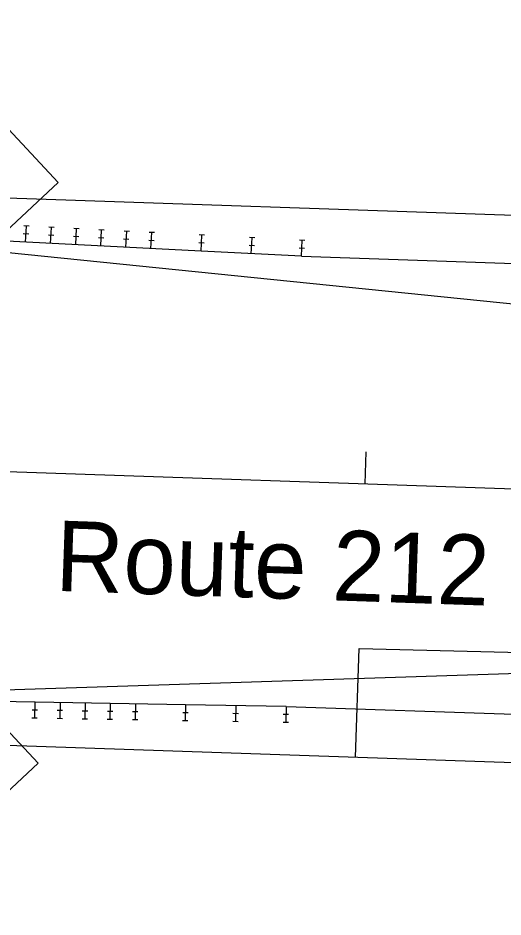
# Model space of a CAD drawing. Extents: x 2191309 to 2193046, y 863659 to 865133.
# Drawn here: x 2191746.5 to 2191776.6, y 865057.5 to 865113.4 of the extents above; entities that cross this region are included whole.
import ezdxf

# ---------------------------------------------------------------- set-up
doc = ezdxf.new("R2010")
doc.units = 0
for name, color, linetype in [('ANNOTATION', 7, 'Continuous'), ('D_Guardrail_Beam_Lt', 7, 'Continuous'), ('D_Guardrail_Beam_Rt', 7, 'Continuous'), ('D_Roadway_Centerline', 7, 'Continuous'), ('D_Roadway_Centerline_Text', 7, 'Continuous'), ('D_Roadway_Edge_Shoulder', 7, 'Continuous'), ('D_Roadway_Edge_TW', 7, 'Continuous'), ('JUNK', 7, 'Continuous')]:
    doc.layers.add(name, color=color, linetype=linetype)

msp = doc.modelspace()

# ---------------------------------------------------------------- linework, layer by layer
at = {"layer": 'D_Guardrail_Beam_Lt'}
for p, q in [((2191747.158, 865100.451), (2191746.825, 865100.468)), ((2191746.94, 865099.461), (2191746.992, 865100.459)), ((2191748.719, 865100.371), (2191748.386, 865100.388)), ((2191748.501, 865099.381), (2191748.552, 865100.379)), ((2191750.279, 865100.29), (2191749.946, 865100.308)), ((2191750.061, 865099.3), (2191750.113, 865100.299)), ((2191751.84, 865100.21), (2191751.507, 865100.227)), ((2191751.622, 865099.22), (2191751.673, 865100.219)), ((2191753.4, 865100.13), (2191753.067, 865100.147)), ((2191753.182, 865099.14), (2191753.234, 865100.139)), ((2191757.864, 865098.9), (2191745.38, 865099.541)), ((2191747.133, 865099.951), (2191746.8, 865099.969)), ((2191748.693, 865099.871), (2191748.36, 865099.888)), ((2191750.253, 865099.791), (2191749.921, 865099.808)), ((2191751.814, 865099.711), (2191751.481, 865099.728)), ((2191753.374, 865099.631), (2191753.041, 865099.648)), ((2191754.935, 865099.551), (2191754.602, 865099.568)), ((2191754.96, 865100.05), (2191754.628, 865100.067)), ((2191754.743, 865099.06), (2191754.794, 865100.059)), ((2191758.081, 865099.89), (2191757.748, 865099.907)), ((2191757.864, 865098.9), (2191757.915, 865099.898)), ((2191761.202, 865099.729), (2191760.869, 865099.746)), ((2191760.984, 865098.739), (2191761.036, 865099.738)), ((2191764.323, 865099.569), (2191763.99, 865099.586)), ((2191764.105, 865098.579), (2191764.157, 865099.578)), ((2191758.056, 865099.39), (2191757.723, 865099.407)), ((2191761.177, 865099.23), (2191760.844, 865099.247)), ((2191764.297, 865099.07), (2191763.965, 865099.087)), ((2191764.105, 865098.579), (2191757.864, 865098.9)), ((2191764.105, 865098.579), (2191793.049, 865097.585)), ((2191756.896, 865070.703), (2191744.398, 865070.919)), ((2191747.522, 865070.865), (2191747.505, 865069.866)), ((2191749.084, 865070.838), (2191749.067, 865069.839)), ((2191750.647, 865070.811), (2191750.629, 865069.812)), ((2191752.209, 865070.784), (2191752.192, 865069.785)), ((2191753.771, 865070.757), (2191753.754, 865069.758)), ((2191756.896, 865070.703), (2191756.879, 865069.703)), ((2191763.145, 865070.595), (2191756.896, 865070.703)), ((2191760.02, 865070.649), (2191760.003, 865069.649)), ((2191763.145, 865070.595), (2191763.128, 865069.595)), ((2191747.68, 865070.363), (2191747.347, 865070.368)), ((2191749.242, 865070.336), (2191748.909, 865070.341)), ((2191750.805, 865070.309), (2191750.471, 865070.314)), ((2191752.367, 865070.282), (2191752.034, 865070.287)), ((2191753.929, 865070.255), (2191753.596, 865070.26)), ((2191757.054, 865070.201), (2191756.721, 865070.206)), ((2191760.178, 865070.147), (2191759.845, 865070.152)), ((2191763.303, 865070.092), (2191762.97, 865070.098)), ((2191747.672, 865069.863), (2191747.338, 865069.868)), ((2191749.234, 865069.836), (2191748.901, 865069.841)), ((2191750.796, 865069.809), (2191750.463, 865069.814)), ((2191752.358, 865069.782), (2191752.025, 865069.787)), ((2191753.921, 865069.755), (2191753.587, 865069.76)), ((2191757.045, 865069.701), (2191756.712, 865069.706)), ((2191760.17, 865069.647), (2191759.836, 865069.652)), ((2191763.294, 865069.593), (2191762.961, 865069.598))]:
    msp.add_line(p, q, dxfattribs=at)
at = {"layer": 'D_Guardrail_Beam_Rt'}
msp.add_line((2191763.145, 865070.595), (2191785.007, 865069.845), dxfattribs=at)
at = {"layer": 'D_Roadway_Centerline'}
msp.add_line((2191489.641, 865093.991), (2191792.637, 865083.591), dxfattribs=at)
at = {"layer": 'D_Roadway_Centerline_Text'}
msp.add_lwpolyline([(2191768.111, 865086.434), (2191768.042, 865084.435)], dxfattribs=at)
at = {"layer": 'D_Roadway_Edge_Shoulder'}
for p, q in [((2191735.145, 865102.575), (2191793.152, 865100.584)), ((2191733.979, 865068.595), (2191784.928, 865066.846))]:
    msp.add_line(p, q, dxfattribs=at)
msp.add_lwpolyline([(2191767.459, 865067.445), (2191767.691, 865074.201), (2191867.759, 865071.744), (2191867.662, 865067.782)], dxfattribs=at)
at = {"layer": 'D_Roadway_Edge_TW'}
for points in [[(2191735.053, 865099.909), (2191784.798, 865094.867), (2191792.961, 865094.587)], [(2191734.07, 865071.26), (2191784.044, 865072.88), (2191792.314, 865072.596)]]:
    msp.add_lwpolyline(points, dxfattribs=at)
at = {"layer": 'JUNK'}
msp.add_lwpolyline([(2191744.185, 865108.278), (2191739.408, 865113.395), (2191728.668, 865103.368), (2191727.463, 865068.247), (2191737.489, 865057.507), (2191747.723, 865067.062), (2191741.653, 865073.562), (2191742.461, 865097.092), (2191748.962, 865103.162), (2191744.185, 865108.278)], dxfattribs=at)

# ---------------------------------------------------------------- texts
at = {"layer": 'ANNOTATION'}
msp.add_text('Route 212', height=4.375, rotation=358.0343, dxfattribs=at).set_placement((2191748.752, 865077.787))

doc.saveas('drawing.dxf')
